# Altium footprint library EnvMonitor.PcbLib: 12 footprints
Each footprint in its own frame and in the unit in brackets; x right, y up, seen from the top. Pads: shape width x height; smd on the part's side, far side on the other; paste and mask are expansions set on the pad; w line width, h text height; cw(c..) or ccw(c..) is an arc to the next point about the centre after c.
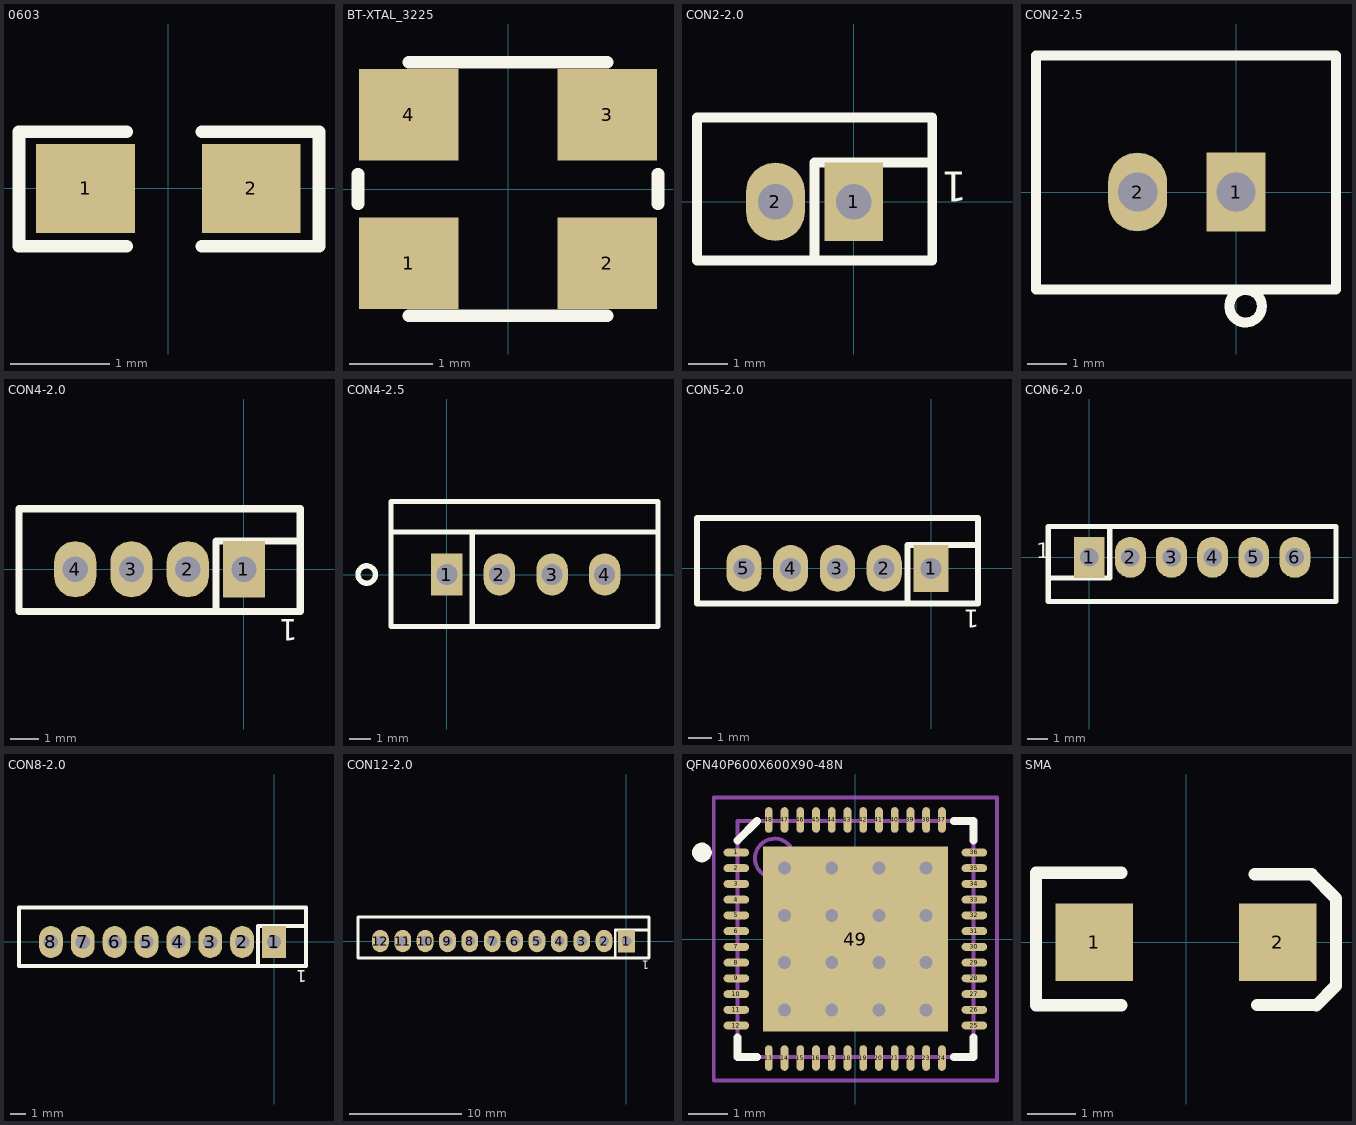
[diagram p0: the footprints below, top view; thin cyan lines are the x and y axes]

## 0603 [mm]
pads (2):
  rect 1x0.9 smd: 1(-0.838,0) 2(0.838,0)
Top Overlay:
  lines w0.127: -0.423,-0.584 -1.511,-0.584 -1.511,0.572 -0.423,0.572 ; 0.339,-0.584 1.524,-0.584 1.524,0.572 0.339,0.572
3D body: height 0.45, standoff 0, extent -0.825,-0.406 0.775,0.394

## BT-XTAL_3225 [mm] "Mercury X32 series"
height 1
pads (4):
  rect 1.2x1.1 smd: 1(-1.194,-0.89) 2(1.194,-0.89) 3(1.194,0.891) 4(-1.194,0.891)
Top Overlay:
  lines w0.152: -1.803,-0.178 -1.803,0.178 ; -1.194,-1.524 1.194,-1.524 ; -1.194,1.524 1.194,1.524 ; 1.803,-0.178 1.803,0.178
3D body: height 0.81, standoff 0.15, extent -1.4,-1.05 1.4,1.05
3D body: height 0.81, standoff 0, extent -1.6,-1.25 1.614,1.25

## CON2-2.0 [mm]
pads (2):
  rect 1.5x2 hole 0.9: 1(0,0)
  oval 1.5x2 hole 0.9: 2(-2,0)
Top Overlay:
  lines w0.254: -1,-1.5 -1,1 2,1 ; -4,-1.5 2,-1.5 2,2.15 -4,2.15 -4,-1.5
  text "1" at 2.89,0.768 h0.76
3D body: height 5.55, standoff -3.45, extent -4,-1.55 2,2.1

## CON2-2.5 [mm]
pads (2):
  rect 1.5x2 hole 1: 1(0,0)
  oval 1.5x2 hole 1: 2(-2.5,0)
Top Overlay:
  circle w0.254: c0.245,-2.9 r0.415
  lines w0.254: -5.08,-2.47 -5.08,3.47 2.54,3.47 2.54,-2.47 -5.08,-2.47

## CON4-2.0 [mm]
pads (4):
  rect 1.5x2 hole 0.9: 1(0,0)
  oval 1.5x2 hole 0.9: 2(-2,0) 3(-4,0) 4(-6,0)
Top Overlay:
  lines w0.254: -1,-1.5 -1,1 2,1 ; -8,-1.5 0.051,-1.5 2,-1.5 2,2.15 -8,2.15 -8,-1.5
  text "1" at 1.905,-1.778 h0.76
3D body: height 5.55, standoff -3.45, extent -8,-1.525 2,2.125

## CON4-2.5 [mm]
pads (4):
  rect 1.5x2 hole 1: 1(0,0)
  oval 1.5x2 hole 1: 2(2.5,0) 3(5,0) 4(7.5,0)
Top Overlay:
  circle w0.254: c-3.815,0 r0.415
  lines w0.254: -2.66,2.025 10.015,2.025 ; 1.2,-2.42 1.2,2.025 ; -2.66,-2.47 -2.66,3.47 10.04,3.47 10.04,-2.179 10.04,-2.47 -2.66,-2.47

## CON5-2.0 [mm]
pads (5):
  rect 1.5x2 hole 0.9: 1(0,0)
  oval 1.5x2 hole 0.9: 2(-2,0) 3(-4,0) 4(-6,0) 5(-8,0)
Top Overlay:
  lines w0.254: -1,-1.5 -1,1 2,1 ; -10,-1.5 2,-1.5 2,2.15 -10,2.15 -10,-1.5
  text "1" at 2.057,-1.778 h0.76
3D body: height 5.55, standoff -3.45, extent -10,-1.5 2,2.15

## CON6-2.0 [mm]
pads (6):
  rect 1.5x2 hole 0.9: 1(0,0)
  oval 1.5x2 hole 0.9: 2(2,0) 3(4,0) 4(6,0) 5(8,0) 6(10,0)
Top Overlay:
  lines w0.254: -2,-1 1,-1 1,1.5 ; -2,-2.15 -2,1.5 12,1.5 12,-2.15 -2,-2.15
  text "1" at -2.591,-0.051 h0.76
3D body: height 5.55, standoff -3.45, extent -2,-2.2 12,1.5

## CON8-2.0 [mm]
pads (8):
  rect 1.5x2 hole 0.9: 1(0,0)
  oval 1.5x2 hole 0.9: 2(-2,0) 3(-4,0) 4(-6,0) 5(-8,0) 6(-10,0) 7(-12,0) 8(-14,0)
Top Overlay:
  lines w0.254: -1,-1.5 -1,1 2,1 ; -16,-1.5 -16,2.15 2,2.15 2,-1.5 -16,-1.5
  text "1" at 2.057,-1.778 h0.76
3D body: height 5.55, standoff -3.45, extent -16,-1.45 2,2.2

## CON12-2.0 [mm]
pads (12):
  rect 1.5x2 hole 0.9: 1(0,0)
  oval 1.5x2 hole 0.9: 2(-2,0) 3(-4,0) 4(-6,0) 5(-8,0) 6(-10,0) 7(-12,0) 8(-14,0) 9(-16,0) 10(-18,0) 11(-20,0) 12(-22,0)
Top Overlay:
  lines w0.254: -1,-1.5 -1,1 2,1 ; -24,-1.5 -24,2.15 2,2.15 2,-1.5 -24,-1.5
  text "1" at 2.057,-1.778 h0.76
3D body: height 5.55, standoff -3.45, extent -24,-1.5 2,2.15

## QFN40P600X600X90-48N [mm] "QFN, 48-Leads, Body 6,0x6,0mm (max), Pitch 0,40mm, IPC Medium Density"
height 0.9
pads (49):
  oval 0.65x0.2 smd: 1(-3.025,2.2) 2(-3.025,1.8) 3(-3.025,1.4) 4(-3.025,1) 5(-3.025,0.6) 6(-3.025,0.2) 7(-3.025,-0.2) 8(-3.025,-0.6) 9(-3.025,-1) 10(-3.025,-1.4) 11(-3.025,-1.8) 12(-3.025,-2.2) 25(3.025,-2.2) 26(3.025,-1.8) 27(3.025,-1.4) 28(3.025,-1) 29(3.025,-0.6) 30(3.025,-0.2) 31(3.025,0.2) 32(3.025,0.6) 33(3.025,1) 34(3.025,1.4) 35(3.025,1.8) 36(3.025,2.2)
  oval 0.2x0.65 smd: 13(-2.2,-3.025) 14(-1.8,-3.025) 15(-1.4,-3.025) 16(-1,-3.025) 17(-0.6,-3.025) 18(-0.2,-3.025) 19(0.2,-3.025) 20(0.6,-3.025) 21(1,-3.025) 22(1.4,-3.025) 23(1.8,-3.025) 24(2.2,-3.025) 37(2.2,3.025) 38(1.8,3.025) 39(1.4,3.025) 40(1,3.025) 41(0.6,3.025) 42(0.2,3.025) 43(-0.2,3.025) 44(-0.6,3.025) 45(-1,3.025) 46(-1.4,3.025) 47(-1.8,3.025) 48(-2.2,3.025)
  rect 4.7x4.7 smd: 49(0,0)
via -1.8,1.8 diameter 0.66 hole 0.33
via -0.6,1.8 diameter 0.66 hole 0.33
via 0.6,1.8 diameter 0.66 hole 0.33
via 1.8,1.8 diameter 0.66 hole 0.33
via -1.8,0.6 diameter 0.66 hole 0.33
via -0.6,0.6 diameter 0.66 hole 0.33
via 0.6,0.6 diameter 0.66 hole 0.33
via 1.8,0.6 diameter 0.66 hole 0.33
via -1.8,-0.6 diameter 0.66 hole 0.33
via -0.6,-0.6 diameter 0.66 hole 0.33
via 0.6,-0.6 diameter 0.66 hole 0.33
via 1.8,-0.6 diameter 0.66 hole 0.33
via -1.8,-1.8 diameter 0.66 hole 0.33
via -0.6,-1.8 diameter 0.66 hole 0.33
via 0.6,-1.8 diameter 0.66 hole 0.33
via 1.8,-1.8 diameter 0.66 hole 0.33
Top Overlay:
  circle w0.25: c-3.9,2.2 r0.125
  lines w0.2: -3,-2.5 -3,-3 -2.5,-3 ; -3,2.5 -2.5,3 ; 2.5,-3 3,-3 3,-2.5 ; 2.5,3 3,3 3,2.5
Mechanical 13:
  circle w0.1: c-2.05,2.05 r0.5
  lines w0.1: -3,-3 -3,3 3,3 3,-3 -3,-3
Mechanical 15:
  lines w0.1: -0.5,0 0.5,0 ; 0,-0.5 0,0.5 ; -3.6,-3.6 -3.6,3.6 3.6,3.6 3.6,-3.6 -3.6,-3.6
3D body: height 0.9, standoff 0, extent -3,-3 3,3

## SMA [mm]
pads (2):
  rect 1.6x1.6 smd: 1(-1.9,0) 2(1.9,0)
Top Overlay:
  lines w0.254: -1.332,-1.308 -3.1,-1.308 -3.1,1.435 -1.332,1.435 ; 1.42,1.4 2.6,1.4 3.1,0.9 3.1,-0.9 2.694,-1.306 ; 1.469,-1.3 2.7,-1.3
3D body: height 2.4, standoff 0, extent -2.287,-1.27 2.313,1.43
